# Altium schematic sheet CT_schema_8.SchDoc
size 391 x 301 mm
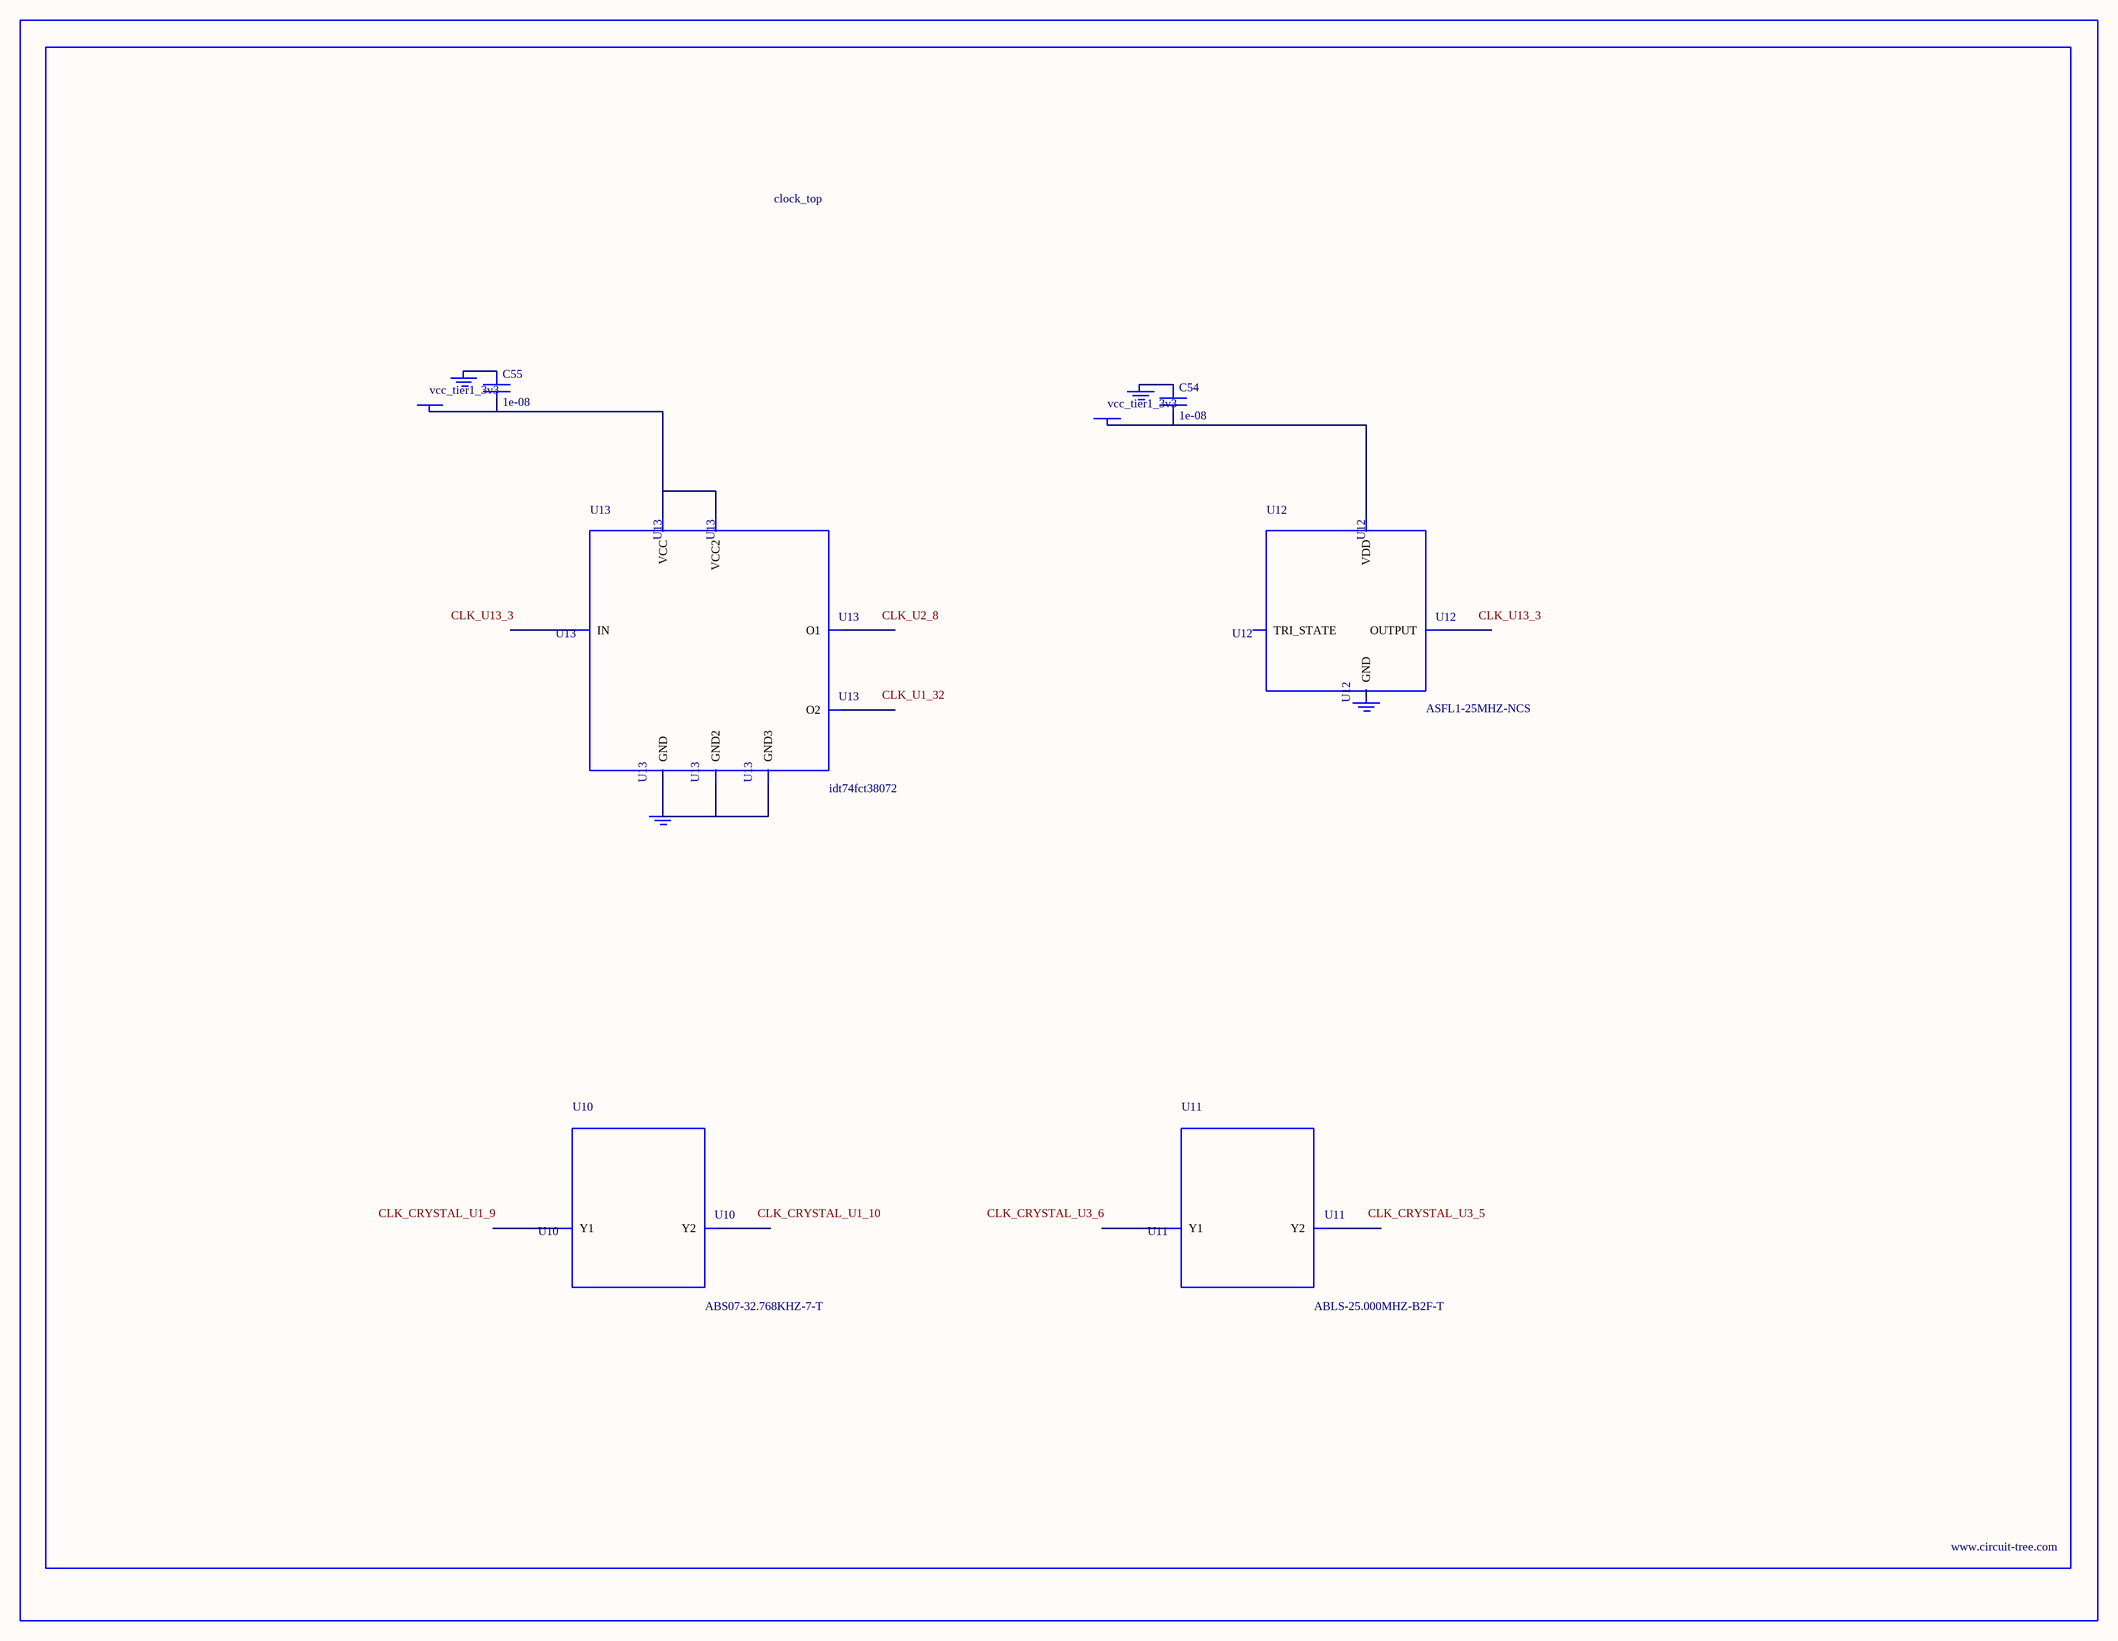
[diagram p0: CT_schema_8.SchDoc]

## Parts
BORDER7  (no value)
C54  1e-08  [C0402]
C55  1e-08  [C0402]
GND_INSTANCE_7_0  (no value)
GND_INSTANCE_7_1  (no value)
GND_INSTANCE_7_2  (no value)
GND_INSTANCE_7_3  (no value)
POWER_INSTANCE_7_0  vcc_tier1_3v3
POWER_INSTANCE_7_1  vcc_tier1_3v3
U10  ABS07-32.768KHZ-7-T  [ABS07-32.768KHZ-7-T]
U11  ABLS-25.000MHZ-B2F-T  [ABLS-25.000MHZ-B2F-T]
U12  ASFL1-25MHZ-NCS  [ASFL1]
U13  idt74fct38072  [IDT74FCT38072]

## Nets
NetC54_1: C54.1 GND_INSTANCE_7_0.0(GND)
NetC54_2: C54.2 POWER_INSTANCE_7_0.0(PWR) U12.4(VDD)
NetC55_1: C55.1 GND_INSTANCE_7_2.0(GND)
NetC55_2: C55.2 POWER_INSTANCE_7_1.0(PWR) U13.1(VCC) U13.2(VCC2)
NetGND_INSTANCE_7_3_0: GND_INSTANCE_7_3.0(GND) U13.4(GND) U13.5(GND2) U13.8(GND3)

Not connected (* = marked no-connect by the designer): GND_INSTANCE_7_1 0(GND); U10 1(Y1) 2(Y2); U11 1(Y1) 2(Y2); U12 1(TRI_STATE) 2(GND) 3(OUTPUT); U13 3(IN) 6(O2) 7(O1)

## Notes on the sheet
- Labels drawn without touching a wire or pin: CLK_CRYSTAL_U1_9, CLK_CRYSTAL_U1_10, CLK_CRYSTAL_U3_5, CLK_CRYSTAL_U3_6, CLK_U1_32, CLK_U2_8, CLK_U13_3

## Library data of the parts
BORDER7 = BORDER_PAGE7
C54 C55 = C0402C103K3RAC
GND_INSTANCE_7_0-GND_INSTANCE_7_3 = GND
POWER_INSTANCE_7_0 POWER_INSTANCE_7_1 = PWR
